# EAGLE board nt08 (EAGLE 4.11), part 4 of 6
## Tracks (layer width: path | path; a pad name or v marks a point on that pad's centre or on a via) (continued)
MC02\  (via drill 0.61) (continued)
  Bottom 0.254: v326.39,117.47 326.39,120.65 325.75,121.28 313.69,121.28 313.69,118.11 314.32,117.47 314.96,117.47 314.96,113.03 IC73.2 | v532.76,285.75 596.9,285.75 600.08,288.93 IC133.11 | v533.4,165.74 483.87,165.74 483.24,165.1 431.8,165.1 431.17,165.74 327.02,165.74 325.75,167 IC74.6
MF00  (via drill 0.61)
  Top 0.254: v525.78,160.02 525.78,157.48 IC115.9 | v429.26,162.56 424.81,167 v424.81,214.63 | v135.89,230.5 136.53,231.14 136.53,269.88 137.79,271.14 137.79,360.05 136.53,361.31 133.99,361.31 133.99,360.68 132.72,359.41 130.81,359.41 130.81,366.39 131.44,367.03 M916_9.V1
  Bottom 0.254: v525.78,160.02 523.24,162.56 v429.26,162.56 | v424.81,214.63 412.12,227.33 275.59,227.33 274.95,226.69 206.38,226.69 201.93,222.25 144.15,222.25 v135.89,230.5
MF00\  (via drill 0.61)
  Top 0.254: v226.06,15.88 217.81,24.13 217.81,107.95 | 217.81,107.95 217.81,140.34 218.44,140.97 v218.44,231.14 | v195.58,234.31 195.58,280.67 IC39.2 | v529.59,115.57 529.59,153.67 528.32,154.94 IC115.8 | v218.44,107.95 217.81,107.95
  Bottom 0.254: v226.06,15.88 227.33,15.88 229.87,13.34 233.04,13.34 234.31,14.61 IC46.2 | v218.44,231.14 215.26,234.31 v195.58,234.31 | v529.59,115.57 441.96,115.57 439.42,118.11 390.52,118.11 389.25,119.38 339.09,119.38 327.02,107.31 219.07,107.31 v218.44,107.95
MF01  (via drill 0.61)
  Top 0.254: v345.44,358.77 330.83,373.38 330.83,443.87 332.74,445.77 331.47,447.04 330.2,447.04 v330.2,446.4
  Bottom 0.254: v345.44,358.77 457.83,358.77 459.74,360.68 586.74,360.68 602.62,376.56 IC136.5 | v330.2,446.4 329.56,447.04 301.62,447.04 298.45,450.21 124.46,450.21 122.56,448.31 55.88,448.31 46.35,438.79 40.64,438.79 39.37,440.06 M916_10.A1
MF01\  (via drill 0.61)
  Top 0.254: v237.49,243.21 v237.49,227.97 237.49,175.9 240.03,173.35 240.03,109.22 241.3,107.95 241.3,17.78 242.57,16.51 IC46.5 | v216.53,246.38 214.63,248.28 v214.63,276.23 | v590.55,241.3 v590.55,360.68
  Bottom 0.254: v237.49,243.21 234.31,246.38 v216.53,246.38 | v214.63,276.23 210.82,280.04 205.1,280.04 203.84,281.31 IC39.5 | v590.55,360.68 605.79,375.92 IC136.6 | v590.55,241.3 582.93,233.68 466.73,233.68 461.64,228.6 275.59,228.6 274.32,227.33 238.12,227.33 v237.49,227.97
MF02  (via drill 0.61)
  Top 0.254: v405.13,401.32 403.86,402.59 v403.86,412.75 | v41.91,412.75 40.64,414.02 40.64,436.25 41.27,436.88 M916_10.B1
  Bottom 0.254: v405.13,401.32 408.31,401.32 415.93,393.7 596.9,393.7 605.15,385.44 IC136.9 | v403.86,412.75 403.23,412.12 57.15,412.12 55.88,413.38 42.55,413.38 v41.91,412.75
MF02\  (via drill 0.61)
  Top 0.254: v247.65,62.23 247.65,24.13 IC46.8 | v220.98,66.04 218.44,68.58 218.44,106.68 219.71,107.95 219.71,236.85 217.81,238.76 v217.81,286.38 217.81,307.98 v220.34,310.51 | v344.17,354.96 331.47,342.26 v331.47,313.06
  Bottom 0.254: v247.65,62.23 243.84,66.04 v220.98,66.04 | v217.81,286.38 215.26,288.93 208.91,288.93 IC39.8 | v344.17,354.96 527.68,354.96 532.13,359.41 607.06,359.41 607.06,378.46 607.7,379.1 608.33,379.1 608.33,383.54 IC136.8 | v331.47,313.06 330.83,313.69 223.52,313.69 v220.34,310.51
MK_BLK_MK
  Bottom 0.254: IC133.1 593.73,281.31 595,281.31 IC133.2
MKT  (via drill 0.61)
  Top 0.254: v329.56,81.92 330.2,82.55 330.2,133.99 328.93,135.25 v328.93,191.13 | v325.12,192.41 325.12,194.31 IC75.9 | v525.14,194.94 525.14,197.49 524.51,198.12 524.51,248.92 525.78,250.19 IC117.9 | v330.83,193.04 329.56,194.31 329.56,295.27 330.2,295.91 v330.2,361.31 330.2,444.5 v331.47,445.77
  Bottom 0.254: v329.56,81.92 324.49,81.92 323.21,80.64 IC72.10 | 328.3,191.77 327.66,192.41 v325.12,192.41 | 328.3,191.77 v328.93,191.13 | v525.14,194.94 521.97,191.77 330.83,191.77 | 330.83,191.77 328.3,191.77 | v330.2,361.31 323.21,361.31 320.68,358.77 IC78.4 | v330.83,193.04 330.83,191.77 | v331.47,445.77 330.83,445.13 302.26,445.13 299.72,447.68 252.09,447.68 251.46,447.04 62.87,447.04 62.87,436.88 61.59,435.61 59.69,435.61 58.42,434.34 M916_10.H2
MKT\  (via drill 0.61)
  Top 0.254: v281.94,385.44 281.94,393.7 283.21,394.97 IC66.5 | v247.01,382.9 246.38,382.27 246.38,288.29 248.92,285.75 v248.92,214.63 | v318.77,205.1 317.5,203.84 317.5,196.85 IC75.12 | v517.52,193.04 517.52,171.45 516.89,170.81 516.89,151.13 518.16,149.86 IC115.3 | v596.9,231.14 596.9,243.84 599.44,246.38 599.44,287.02 598.17,288.29 IC133.12
  Bottom 0.254: v281.94,385.44 279.4,382.9 v247.01,382.9 | v248.92,214.63 249.56,214 288.29,214 297.18,205.1 v318.77,205.1 | 514.35,196.22 513.72,196.85 469.26,196.85 468,195.58 328.3,195.58 IC75.8 327.02,196.22 325.75,197.49 319.4,197.49 318.13,196.22 IC75.12 | 514.35,196.22 v517.52,193.04 | v596.9,231.14 561.98,196.22 514.35,196.22
MKTK  (via drill 0.61)
  Top 0.254: v121.28,485.77 121.28,371.48 v120.65,370.84
  Bottom 0.254: v121.28,485.77 92.71,485.77 74.3,504.19 54.61,504.19 50.16,508.63 IC6.8 | v120.65,370.84 116.84,370.84 M916_9.P1
MKTK\  (via drill 0.61)
  Top 0.254: v50.8,58.42 54.61,62.23 54.61,123.19 53.34,124.46 53.34,179.71 55.24,181.61 55.24,238.76 57.15,240.66 57.15,261.62 53.34,265.43 53.34,454.66 53.98,455.3 53.98,501.01 46.99,508 IC6.9 | v161.29,514.35 161.29,553.72 160.02,554.99 IC32.11
  Bottom 0.254: v50.8,58.42 38.1,58.42 33.66,53.98 IC10.1 | v161.29,514.35 160.66,514.99 119.38,514.99 115.57,511.18 48.9,511.18 47.62,509.9 IC6.9
MOVE\  (via drill 0.61)
  Top 0.254: v539.12,421 537.21,419.1 537.21,325.75 537.85,325.12 537.85,178.44 539.75,176.53 539.75,76.2 539.12,75.56 v539.12,19.68
  Bottom 0.254: 539.12,20.32 557.53,20.32 559.43,22.23 IC123.11 | 539.12,20.32 56.52,20.32 55.88,20.95 40.01,20.95 38.73,22.23 IC9.12 | v539.12,421 545.47,421 IC124.1 | v539.12,19.68 539.12,20.32
MR00  (via drill 0.61)
  Top 0.254: v268.61,537.85 268.61,540.38 246.38,562.61 246.38,572.77 245.11,574.04 IC57.9 | v291.46,522.61 295.91,518.16 295.91,323.85 297.18,322.58 v297.18,262.89 | v313.69,262.25 317.5,258.44 317.5,252.73 IC76.12
  Bottom 0.254: v268.61,537.85 283.85,522.61 v291.46,522.61 | v297.18,262.89 297.81,262.25 v313.69,262.25
MR00\  (via drill 0.61)
  Top 0.254: v162.56,458.47 162.56,407.67 160.02,405.13 IC30.11 | v187.96,459.74 189.87,461.64 189.87,537.85 199.39,547.37 199.39,557.53 219.71,577.85 247.65,577.85 247.65,576.58 IC57.8
  Bottom 0.254: v162.56,458.47 163.83,459.74 v187.96,459.74
MR01  (via drill 0.61)
  Top 0.254: v476.25,285.12 476.25,265.43 474.98,264.16 IC108.2 | v89.53,347.35 89.53,369.57 90.17,370.2 M916_9.E1 | v406.4,342.26 v406.4,296.55
  Bottom 0.254: v476.25,285.12 450.21,285.12 446.4,288.93 IC95.9 445.13,290.19 443.87,291.46 411.48,291.46 v406.4,296.55 | v89.53,347.35 93.34,343.54 125.73,343.54 126.36,344.17 185.42,344.17 186.69,345.44 228.6,345.44 230.5,347.35 286.38,347.35 288.29,345.44 346.07,345.44 348.62,347.98 400.69,347.98 v406.4,342.26
MR01\  (via drill 0.61)
  Top 0.254: v445.77,256.54 447.04,257.81 447.04,283.21 441.96,288.29 441.96,290.83 442.6,291.46 448.31,291.46 448.31,290.83 IC95.8 | v170.18,465.45 172.72,462.92 172.72,363.22 173.35,362.58 173.35,249.56 v172.72,248.92
  Bottom 0.254: 316.87,245.75 318.77,247.65 353.06,247.65 358.14,252.73 377.19,252.73 379.73,255.27 396.24,255.27 397.51,256.54 v445.77,256.54 | 316.87,245.75 315.6,244.47 IC76.2 | v170.18,465.45 161.93,465.45 155.57,471.81 IC31.2 | v172.72,248.92 289.56,248.92 292.74,245.75 316.87,245.75
N$1  (via drill 0.61)
  Top 0.254: v265.43,188.59 264.16,189.87 v264.16,243.21 | v226.06,247.65 222.88,250.82 222.88,288.93 224.79,290.83 224.79,296.55 225.43,297.18 225.43,349.25 224.79,349.88 224.79,389.25 224.16,389.89 v224.16,509.9
  Bottom 0.254: v265.43,188.59 276.23,188.59 277.5,187.32 IC61.3 | v264.16,243.21 259.71,247.65 v226.06,247.65 | v224.16,509.9 231.78,509.9 IC55.1
N$2  (via drill 0.61)
  Top 0.254: IC120.13 516.25,422.27 517.52,422.27 IC120.12 | v535.3,421 535.3,326.39 537.21,324.49 537.21,13.34 525.14,13.34 524.51,13.97 524.51,20.32 523.24,21.59 IC112.10 | IC120.10 523.88,422.27 525.14,422.27 IC120.9
  Bottom 0.254: v535.3,421 527.68,421 | 527.68,421 526.41,422.27 IC120.9 | 527.68,421 520.07,421 518.79,422.27 IC120.12
N$3  (via drill 0.61)
  Top 0.254: v45.09,537.85 38.1,530.86 38.1,474.98 39.37,473.71 IC15.3 | v282.57,542.92 285.75,546.1 285.75,547.37 IC69.6
  Bottom 0.254: v45.09,537.85 48.9,541.65 210.19,541.65 211.46,542.92 v282.57,542.92
N$4
  Top 0.254: M916_19.R2 -0.64,221.62 1.27,223.52 1.27,224.16 M916_19.S2
N$5  (via drill 0.61)
  Top 0.254: v485.14,434.98 v488.31,438.15
  Bottom 0.254: v488.31,438.15 510.54,438.15 525.14,452.75 IC121.6 | v485.14,434.98 478.79,428.62 283.85,428.62 273.69,418.46 94.61,418.46 93.34,419.74 59.69,419.74 58.42,421 M916_2.H2
N$6  (via drill 0.61)
  Top 0.254: IC121.9 525.14,460.38 523.88,460.38 IC121.10 522.61,460.38 516.89,454.66 | 516.89,460.38 517.52,460.38 IC121.12 | 516.89,460.38 516.25,460.38 IC121.13 | v515.62,426.08 516.89,427.36 516.89,454.66 | 516.89,454.66 516.89,460.38
  Bottom 0.254: v515.62,426.08 383.54,426.08 372.11,414.65 144.78,414.65 144.15,414.02 11.43,414.02 -14.61,387.99 -44.45,387.99 -44.45,230.5 -36.83,222.88 -28.57,222.88 -27.3,221.62 M916_19.F2
N$7
  Top 0.254: IC16.5 82.55,16.51 82.55,19.05 80.01,21.59 IC16.11 80.01,24.13 80.01,90.17 IC17.4
N$8
  Top 0.254: IC123.1 551.82,14.61 530.86,-6.35 -34.92,-6.35 -34.92,454.66 -27.3,462.28 M916_23.F2
N$10  (via drill 0.61)
  Top 0.254: v375.92,153.67 v375.92,38.1 | v373.38,156.21 374.01,156.84 374.01,320.68 381,327.66 381,454.66 384.81,458.47 v384.81,471.17
  Bottom 0.254: v375.92,38.1 370.2,32.38 314.32,32.38 313.06,33.66 IC71.1 | v373.38,156.21 v375.92,153.67 | v384.81,471.17 390.52,476.88 404.5,476.88 407.04,479.43 IC90.8
N$11  (via drill 0.61)
  Top 0.254: v355.6,36.83 374.65,36.83 374.65,154.94 376.56,156.84 376.56,318.13 381.63,323.21 381.63,454.02 386.08,458.47 v386.08,476.25
  Bottom 0.254: v355.6,36.83 325.12,36.83 323.21,34.92 IC71.5 | v386.08,476.25 387.35,477.52 402.59,477.52 403.86,478.79 403.86,481.96 401.95,481.96 400.69,480.69 IC90.11
N$12
  Top 0.254: M916_23.D2 -32.38,462.92 -30.48,464.82 -30.48,465.45 M916_23.E2
N$13  (via drill 0.61)
  Top 0.254: v289.56,219.07 289.56,196.85 288.29,195.58 IC61.8
  Bottom 0.254: M916_1.H2 97.79,224.16 100.33,221.62 M916_1.J2 100.97,221.62 103.5,224.16 M916_1.K2 104.14,224.79 106.05,224.79 107.31,226.06 118.75,226.06 121.92,222.88 133.35,222.88 133.35,220.34 134.62,219.07 v289.56,219.07
N$14
  Top 0.254: M916_2.D2 48.9,418.46 50.8,420.37 50.8,421 M916_2.E2
N$15  (via drill 0.61)
  Top 0.254: v515.62,18.41 515.62,21.59 IC112.13 | v74.3,18.41 71.12,21.59 71.12,87.63 73.66,90.17 73.66,212.72 67.94,218.44 67.94,413.38 v64.77,416.56
  Bottom 0.254: v515.62,18.41 514.99,19.05 74.93,19.05 v74.3,18.41 | v64.77,416.56 56.52,416.56 55.24,417.83 M916_2.F2
N$16  (via drill 0.61)
  Top 0.254: IC18.4 80.64,243.21 81.92,243.21 IC18.5 82.55,242.57 83.82,241.3 83.82,238.12 83.19,237.49 83.19,223.52 83.82,222.88 83.82,220.34 83.19,219.71 83.19,214.63 80.01,211.46 80.01,149.86 v81.28,148.59 | v518.16,26.67 518.16,24.13 IC112.12 | v226.06,28.57 222.25,32.38 v222.25,147.32
  Bottom 0.254: v518.16,26.67 516.89,27.94 286.38,27.94 285.75,28.57 v226.06,28.57 | v222.25,147.32 220.98,148.59 v81.28,148.59
N$17  (via drill 0.61)
  Top 0.254: IC77.3 317.5,267.97 320.04,270.51 320.04,273.05 IC77.11 320.04,275.59 320.04,298.45 v316.23,302.26
  Bottom 0.254: v316.23,302.26 182.88,302.26 181.61,303.53 97.16,303.53 95.89,302.26 14.61,302.26 13.97,302.89 -25.4,302.89 -32.38,309.88 M916_21.D2
N$18  (via drill 0.61)
  Top 0.254: v281.94,216.53 281.31,215.9 281.31,196.22 280.67,195.58 IC61.11 | v119.38,219.07 v121.92,216.53
  Bottom 0.254: M916_1.P2 115.57,224.16 110.49,224.16 M916_1.M2 109.22,224.16 107.95,222.88 107.95,221.62 112.39,221.62 M916_1.N2 113.67,220.98 117.47,220.98 v119.38,219.07 | v281.94,216.53 281.31,215.9 133.35,215.9 132.72,216.53 v121.92,216.53
N$19
  Bottom 0.254: M916_1.H1 96.52,230.5 96.52,226.06 95.89,225.43 95.89,220.34 99.06,220.34 99.69,219.71 104.78,219.71 106.05,220.98 M916_1.L2
N$20
  Top 0.254: M916_2.R2 80.64,418.46 82.55,420.37 82.55,421 M916_2.S2
N$21
  Bottom 0.254: M916_1.D2 88.27,221.62 90.81,224.16 M916_1.E2
N$22  (via drill 0.61)
  Top 0.254: v125.09,465.45 124.46,464.82 124.46,344.17 128.27,340.36 128.27,315.6 127.64,314.96 127.64,291.46 130.18,288.93 130.18,217.17 129.54,216.53 127.64,216.53 127.64,219.71 126.36,220.98 M916_1.T2
  Bottom 0.254: v125.09,465.45 113.03,477.52 93.34,477.52 92.71,476.88 40.01,476.88 37.47,479.43 IC15.13
N$23  (via drill 0.61)
  Top 0.254: v32.38,465.45 30.48,463.55 30.48,421.64 28.57,419.74 28.57,389.25 29.21,388.62 29.21,356.24 27.3,354.33 v27.3,233.04
  Bottom 0.254: v32.38,465.45 37.47,465.45 43.81,471.81 IC15.5 | v27.3,233.04 34.29,226.06 91.44,226.06 93.34,224.16 93.34,221.62 M916_1.F2
N$24  (via drill 0.61)
  Top 0.254: v527.05,506.73 527.05,387.35 528.32,386.08 IC119.8
  Bottom 0.254: v527.05,506.73 526.41,506.1 314.96,506.1 306.7,497.84 304.8,497.84 M916_12.K2
N$25
  Bottom 0.254: M916_1.R2 120.02,220.98 120.65,220.34 124.46,220.34 125.09,219.71 130.18,219.71 131.44,220.98 M916_1.V2
N$26
  Top 0.254: M916_1.S2 121.92,224.79 121.92,230.5 M916_1.S1
N$27
  Bottom 0.254: M916_21.N2 -6.99,310.51 -5.71,311.79 0,311.79 1.27,313.06 M916_21.S2
N$28  (via drill 0.61)
  Top 0.254: v315.6,51.44 315.6,70.48 314.96,71.12 IC72.2 | v448.31,56.52 450.21,58.42 450.21,323.85 v453.39,327.02
  Bottom 0.254: v315.6,51.44 316.23,50.8 440.69,50.8 446.4,56.52 v448.31,56.52 | v453.39,327.02 469.26,327.02 471.81,329.56 475.62,329.56 476.88,328.3 IC109.12
N$29
  Top 0.254: M916_12.D2 288.93,494.67 290.83,496.57 290.83,497.2 M916_12.E2
N$30
  Bottom 0.254: IC122.3 518.79,511.18 520.07,512.45 523.88,512.45 524.51,511.81 524.51,506.73 309.25,506.73 297.18,494.67 295.27,494.67 M916_12.F2
N$31  (via drill 0.61)
  Top 0.254: IC19.10 84.45,268.61 85.72,268.61 IC19.9 86.36,270.51 86.36,285.75 92.71,292.1 92.71,330.2 v93.98,331.47 | v512.45,501.01 520.7,509.27 IC122.4 | v299.72,484.5 298.45,483.24 v298.45,340.36
  Bottom 0.254: v512.45,501.01 499.11,487.68 417.19,487.68 414.02,484.5 v299.72,484.5 | v298.45,340.36 297.81,341 207.01,341 197.49,331.47 v93.98,331.47
N$33  (via drill 0.61)
  Top 0.254: v5.08,543.56 2.54,546.1 IC7.10 | v245.11,546.74 266.7,525.14 v266.7,398.14
  Bottom 0.254: v5.08,543.56 6.35,542.29 104.14,542.29 113.03,551.18 125.73,551.18 127,549.91 127,546.1 244.47,546.1 v245.11,546.74 | v266.7,398.14 283.85,398.14 285.12,396.88 IC66.6
N$34  (via drill 0.61)
  Top 0.254: v353.06,24.77 344.81,33.02 344.81,225.43 342.26,227.97 v342.26,314.96 | v7.62,307.98 3.81,307.98 3.81,385.44 4.45,386.08 M916_22.T2
  Bottom 0.254: v353.06,24.77 353.69,25.4 562.61,25.4 564.51,23.5 IC123.9 | v342.26,314.96 151.13,314.96 147.32,311.15 14.61,311.15 11.43,307.98 v7.62,307.98
N$35
  Bottom 0.254: IC8.9 4.45,586.11 2.54,588.01 -8.89,588.01 -46.35,550.54 -46.35,-6.99 456.56,-6.99 474.98,11.43 485.14,11.43 487.05,13.34 IC104.8
N$36  (via drill 0.61)
  Top 0.254: v495.94,432.44 496.57,431.8 496.57,196.22 500.38,192.41 v500.38,149.86
  Bottom 0.254: v495.94,432.44 492.12,436.25 447.68,436.25 446.4,434.98 IC99.6 | v500.38,149.86 501.01,150.5 513.72,150.5 514.99,149.22 IC115.2
N$37
  Top 0.254: M916_12.R2 320.68,494.67 322.58,496.57 322.58,497.2 M916_12.S2
N$38
  Top 0.254: IC116.3 518.16,204.47 518.16,209.55 IC116.12
N$39
  Bottom 0.254: IC116.13 516.25,210.19 521.34,205.1 523.88,205.1 525.14,203.84 IC116.6
N$40
  Bottom 0.254: M916_20.M2 -10.16,236.85 -8.89,235.59 9.53,235.59 10.79,234.31 M916_20.V2
N$41
  Bottom 0.254: M916_20.P1 -3.81,243.21 -2.54,241.94 9.53,241.94 10.79,240.66 M916_20.V1
N$42  (via drill 0.61)
  Top 0.254: v483.87,120.02 483.87,113.03 485.14,111.76 IC106.6
  Bottom 0.254: v483.87,120.02 479.43,120.02 478.15,118.75 IC106.12
N$43
  Top 0.254: IC17.3 77.47,92.71 77.47,97.79 IC17.12
N$44  (via drill 0.61)
  Top 0.254: v474.98,85.72 478.79,89.53 478.79,111.76 480.06,113.03 480.06,116.84 IC106.11
  Bottom 0.254: v474.98,85.72 319.4,85.72 314.96,81.28 IC72.13
N$45
  Bottom 0.254: IC17.13 75.56,98.42 76.83,97.16 85.72,97.16 87,98.42 IC17.8
N$46  (via drill 0.61)
  Top 0.254: v34.29,160.66 40.64,154.31 40.64,123.19 40.01,122.56 40.01,118.75 IC11.11
  Bottom 0.254: v34.29,160.66 -45.72,160.66 -45.72,549.91 -8.26,587.38 -4.45,587.38 -3.17,586.11 IC8.12
N$47  (via drill 0.61)
  Top 0.254: v327.66,476.88 343.54,461.01 v343.54,445.13 | v440.69,446.4 441.96,445.13 441.96,436.88 443.23,435.61 IC99.5
  Bottom 0.254: v327.66,476.88 290.19,476.88 IC68.8 | v343.54,445.13 344.17,445.77 415.29,445.77 415.93,446.4 v440.69,446.4
N$48  (via drill 0.61)
  Top 0.254: v358.14,38.1 360.68,40.64 v360.68,184.78
  Bottom 0.254: v358.14,38.1 355.6,35.56 354.96,35.56 354.33,36.2 327.02,36.2 325.75,34.92 IC71.6 | v360.68,184.78 475.62,184.78 476.25,185.42 476.25,188.59 478.15,188.59 479.43,187.32 IC107.4
N$49  (via drill 0.61)
  Top 0.254: v262.89,479.43 257.81,474.35 257.81,393.06 255.27,390.52 255.27,340.36 257.18,338.45 257.18,304.17 263.52,297.81 263.52,251.46 262.89,250.82 262.89,233.68 263.52,233.04 263.52,163.83 267.33,160.02 267.33,44.45 265.43,42.55 v265.43,9.53
  Bottom 0.254: v262.89,479.43 282.57,479.43 283.85,478.15 IC68.10 | v265.43,9.53 266.7,8.26 323.21,8.26 327.02,4.45 IC70.8
N$50  (via drill 0.61)
  Top 0.254: v516.89,367.67 516.89,254 518.16,252.73 IC117.12
  Bottom 0.254: v516.89,367.67 502.29,382.27 480.06,382.27 478.15,384.18 IC110.12
N$51  (via drill 0.61)
  Top 0.254: v328.93,97.79 328.93,82.55 327.66,81.28 IC72.8 | v466.09,103.5 470.54,107.95 v470.54,260.35
  Bottom 0.254: v328.93,97.79 334.64,103.5 v466.09,103.5 | v470.54,260.35 471.17,260.99 478.15,260.99 479.43,262.25 IC108.4
N$52  (via drill 0.61)
  Top 0.254: v477.52,189.87 476.25,191.13 476.25,250.19 474.35,252.09 474.35,258.44 477.52,261.62 IC108.3
  Bottom 0.254: v477.52,189.87 481.96,189.87 484.5,187.32 IC107.6
N$53
  Bottom 0.254: IC117.13 516.25,250.82 521.34,245.75 523.88,245.75 525.14,244.47 IC117.6
N$54
  Top 0.254: IC106.3 477.52,111.76 478.79,113.03 478.79,257.81 482.6,261.62 IC108.5
N$55  (via drill 0.61)
  Top 0.254: v382.27,479.43 386.08,483.24 386.08,494.03 387.35,495.3 388.62,495.3 388.62,384.81 382.9,379.1 382.9,203.2 377.19,197.49 377.19,38.1 v334.01,-5.08
  Bottom 0.254: v382.27,479.43 288.93,479.43 287.65,478.15 IC68.9 | v334.01,-5.08 333.38,-5.71 327.02,-5.71 325.75,-4.45 IC70.6
N$56  (via drill 0.61)
  Top 0.254: v13.34,471.81 13.34,468.63 9.53,464.82 9.53,290.19 6.99,290.19 5.71,291.46 IC2.6 | v281.94,485.14 281.94,478.79 IC68.11
  Bottom 0.254: v13.34,471.81 13.97,472.44 22.86,472.44 34.92,484.5 177.16,484.5 177.8,485.14 v281.94,485.14
N$58  (via drill 0.61)
  Top 0.254: v57.78,478.15 59.69,476.25 59.69,328.3 60.33,327.66 v60.33,306.07 | v254.63,306.07 255.27,305.44 255.27,219.07 261.62,212.72 v261.62,187.96
  Bottom 0.254: v57.78,478.15 48.9,478.15 47.62,479.43 IC15.9 | v60.33,306.07 157.48,306.07 158.12,306.7 254,306.7 v254.63,306.07 | v261.62,187.96 265.43,184.15 269.88,184.15 271.14,182.88 283.21,182.88 285.75,185.42 IC61.6
N$59  (via drill 0.61)
  Top 0.254: v511.18,13.34 495.3,29.21 v495.3,193.04
  Bottom 0.254: v511.18,13.34 516.25,13.34 517.52,14.61 IC112.3 | v495.3,193.04 492.12,196.22 481.96,196.22 480.69,194.94 IC107.11
N$60  (via drill 0.61)
  Top 0.254: v456.56,76.83 457.2,77.47 v457.2,267.97 | v486.41,267.33 487.68,268.61 487.68,269.24 IC108.8
  Bottom 0.254: v456.56,76.83 316.87,76.83 313.06,73.03 IC72.1 | v457.2,267.97 457.83,267.33 v486.41,267.33
N$61  (via drill 0.61)
  Top 0.254: v456.56,69.22 458.47,71.12 458.47,142.24 459.74,143.51 459.74,256.54 464.19,260.99 464.19,358.14 466.09,360.05 v466.09,373.38
  Bottom 0.254: v456.56,69.22 455.93,69.85 322.58,69.85 320.68,71.75 IC72.4 | v466.09,373.38 471.81,379.1 483.24,379.1 484.5,377.82 IC110.6
N$62  (via drill 0.61)
  Top 0.254: v328.93,74.3 328.93,44.45 327.66,43.18 IC71.8
  Bottom 0.254: v328.93,74.3 324.49,74.3 323.21,73.03 IC72.5
N$63  (via drill 0.61)
  Top 0.254: v305.44,177.8 305.44,195.58 307.98,198.12 307.98,305.44 306.7,306.7 306.7,367.67 315.6,367.67 316.23,367.03 316.23,360.68 317.5,359.41 IC78.3
  Bottom 0.254: v305.44,177.8 320.04,177.8 321.94,175.9 IC74.10
N$64  (via drill 0.61)
  Top 0.254: v97.16,32.38 88.27,23.5 IC16.8 | v172.72,41.27 173.99,42.55 173.99,105.41 173.35,106.05 173.35,116.2 176.53,119.38 v176.53,259.08 | v220.98,262.25 222.25,263.52 v222.25,358.14 | IC65.5 282.57,357.5 281.31,357.5 IC65.4
  Bottom 0.254: v97.16,32.38 106.05,41.27 v172.72,41.27 | v176.53,259.08 179.71,262.25 v220.98,262.25 | v222.25,358.14 224.16,360.05 278.76,360.05 280.04,358.77 IC65.4
N$65
  Bottom 0.254: IC107.12 478.15,193.68 479.43,192.41 485.77,192.41 487.05,193.68 IC107.8
N$66  (via drill 0.61)
  Top 0.254: v177.8,356.24 178.44,355.6 178.44,264.16 180.34,262.25 180.34,258.44 177.8,255.91 177.8,12.06 80.64,12.06 78.11,14.61 IC16.3 | IC65.2 274.95,357.5 273.69,357.5 IC65.1
  Bottom 0.254: v177.8,356.24 212.72,356.24 214,357.5 221.62,357.5 222.25,356.87 273.05,356.87 IC65.1
N$67  (via drill 0.61)
  Top 0.254: v-18.41,304.17 -18.41,235.59 -19.68,234.31 M916_20.J2
  Bottom 0.254: v-18.41,304.17 2.54,304.17 10.16,311.79 127,311.79 132.08,316.87 337.82,316.87 340.36,319.4 364.49,319.4 365.12,318.77 379.1,318.77 387.35,310.51 606.42,310.51 607.7,309.25 IC134.8
N$68
  Top 0.254: M916_20.D2 -32.38,234.31 -27.94,234.31 -27.94,236.85 -24.13,240.66 -24.13,243.21 M916_20.H1
N$69
  Bottom 0.254: M916_20.A1 -41.91,243.21 -36.83,243.21 M916_20.C1
N$70  (via drill 0.61)
  Top 0.254: v97.16,300.99 98.42,302.26 98.42,374.65 112.39,388.62 v112.39,420.37 | v280.67,426.72 284.48,430.53 284.48,450.85 286.38,452.75 286.38,469.26 IC68.6
  Bottom 0.254: v97.16,300.99 86.36,300.99 83.19,297.81 6.99,297.81 5.71,299.08 IC2.9 | v112.39,420.37 120.02,427.99 143.51,427.99 144.78,426.72 v280.67,426.72
N$71  (via drill 0.61)
  Top 0.254: v347.98,508.63 347.98,507.37 326.39,485.77 326.39,360.68 325.12,359.41 IC78.6
  Bottom 0.254: v347.98,508.63 348.62,508 510.54,508 512.45,509.9 IC122.1
N$72  (via drill 0.61)
  Top 0.254: v0,321.94 0,300.99 IC2.11 | v275.59,323.85 276.86,325.12 276.86,467.36 278.13,468.63 278.13,474.98 279.4,476.25 IC68.12
  Bottom 0.254: v0,321.94 3.17,325.12 72.39,325.12 73.66,323.85 v275.59,323.85
N$73  (via drill 0.61)
  Top 0.254: v283.21,292.74 283.21,290.83 IC63.10 | v270.51,292.1 270.51,267.33 271.14,266.7 271.14,254.63 269.88,253.37 269.88,183.51 271.78,181.61 v271.78,113.03
  Bottom 0.254: v283.21,292.74 282.57,292.1 v270.51,292.1 | v271.78,113.03 272.42,112.39 283.85,112.39 285.12,111.12 IC60.6
N$76
  Top 0.254: IC118.3 518.16,318.77 519.43,317.5 519.43,214.63 521.97,212.09 521.97,180.97 521.34,180.34 521.34,158.12 521.97,157.48 521.97,120.65 520.7,119.38 IC114.11
N$77  (via drill 0.61)
  Top 0.254: v166.37,299.72 168.91,302.26 v168.91,360.68
  Bottom 0.254: v166.37,299.72 102.87,299.72 100.33,302.26 97.16,302.26 96.52,301.62 9.53,301.62 8.26,300.36 IC2.8 | v168.91,360.68 172.09,363.86 283.85,363.86 285.12,365.12 IC65.9
N$78  (via drill 0.61)
  Top 0.254: v275.59,389.25 275.59,367.03 IC65.13 | v332.11,392.43 345.44,405.76 v345.44,491.49 | v512.45,502.29 515.62,505.46 515.62,509.27 IC122.2
  Bottom 0.254: v275.59,389.25 278.76,392.43 v332.11,392.43 | v345.44,491.49 346.71,492.76 389.89,492.76 393.06,495.94 506.1,495.94 v512.45,502.29
N$79  (via drill 0.61)
  Top 0.254: v547.37,121.28 546.74,121.92 546.74,419.74 547.37,420.37 v547.37,515.62
  Bottom 0.254: v547.37,121.28 526.41,121.28 523.88,118.75 IC114.10 | v547.37,515.62 542.29,520.7 485.14,520.7 483.24,518.79 IC111.10
N$80  (via drill 0.61)
  Top 0.254: v196.85,563.88 v177.8,582.93 | v290.19,560.07 309.25,541.02 309.25,376.56 318.77,367.03 318.77,300.99 321.94,297.81 v321.94,294.64 | v356.24,292.74 358.14,290.83 358.14,223.52 360.68,220.98 360.68,209.55 363.86,206.38 363.86,142.88 368.3,138.43 368.3,135.89 M916_15.U2
  Bottom 0.254: v177.8,582.93 -2.54,582.93 -4.45,584.84 IC8.13 | v196.85,563.88 200.66,560.07 v290.19,560.07 | v321.94,294.64 323.85,292.74 v356.24,292.74
N$81
  Top 0.254: IC108.12 477.52,271.78 480.69,274.95 480.69,318.13 481.33,318.77 481.33,515.62 480.06,516.89 IC111.11
N$82  (via drill 0.61)
  Top 0.254: v291.46,507.37 288.93,509.9 288.93,546.74 289.56,547.37 289.56,552.45 288.29,553.72 288.29,554.99 IC69.8
  Bottom 0.254: v291.46,507.37 520.07,507.37 522.61,509.9 IC122.5
N$83
  Top 0.254: IC5.12 -2.54,450.85 -5.71,454.02 -5.71,534.03 -3.81,535.94 -3.81,568.96 3.81,576.58 3.81,580.39 7.62,584.2 IC8.8
N$84
  Bottom 0.254: IC11.3 38.73,109.86 40.01,109.86 IC11.4
N$85  (via drill 0.61)
  Top 0.254: v313.69,370.84 317.5,367.03 IC78.12 | v136.53,360.05 136.53,271.14 134.62,269.24 134.62,221.62 136.53,219.71 136.53,178.44 135.25,177.16 v135.25,114.94
  Bottom 0.254: IC11.2 36.2,109.86 37.47,108.58 43.81,108.58 45.09,109.86 IC11.6 46.35,109.86 50.8,105.41 82.55,105.41 84.45,107.31 127.64,107.31 v135.25,114.94 | v313.69,370.84 264.16,370.84 263.52,370.2 146.69,370.2 v136.53,360.05
N$86
  Top 0.254: IC69.13 275.59,557.53 283.85,565.78 283.85,574.67 284.48,575.31 312.42,575.31 312.42,497.84 314.96,495.3 314.96,372.11 320.04,367.03 IC78.11
N$88
  Top 0.254: M916_23.R2 -0.64,462.92 1.27,464.82 1.27,465.45 M916_23.S2
N$91
  Top 0.254: IC60.11 280.67,119.38 279.4,120.65 279.4,198.12 280.67,199.39 280.67,241.3 279.4,242.57 279.4,317.5 280.67,318.77 IC64.4
N$92  (via drill 0.61)
  Top 0.254: v268.61,49.53 267.97,50.16 267.97,181.61 266.7,182.88 266.7,233.68 266.06,234.31 266.06,248.92 v267.97,250.82
  Bottom 0.254: v268.61,49.53 273.05,49.53 280.04,42.55 IC59.11 | v267.97,250.82 270.51,253.37 281.31,253.37 282.57,252.09 IC62.10
N$93  (via drill 0.61)
  Top 0.254: 596.9,33.02 596.26,32.38 594.36,32.38 594.36,35.56 593.09,36.83 593.09,40.64 IC126.14 | 596.9,33.02 597.53,33.66 IC126.3 | v599.44,85.72 599.44,76.2 596.9,73.66 596.9,33.02
  Bottom 0.254: v599.44,85.72 609.6,85.72 609.6,111.76 607.06,114.3 607.06,137.79 605.79,139.06 605.79,157.48 IC129.6
N$94  (via drill 0.61)
  Top 0.254: v611.5,166.37 610.87,165.74 610.87,85.09 609.6,83.82 609.6,36.83 608.33,35.56 IC126.7
  Bottom 0.254: IC126.7 608.33,35.56 603.25,40.64 IC126.10 | v611.5,166.37 608.97,166.37 IC129.8
N$95  (via drill 0.61)
  Top 0.254: v610.87,83.82 612.77,85.72 612.77,236.85 608.33,241.3 IC131.8
  Bottom 0.254: IC127.3 598.17,73.66 593.09,78.74 IC127.14 593.73,80.64 596.26,83.19 610.24,83.19 v610.87,83.82
N$96  (via drill 0.61)
  Top 0.254: v599.44,189.23 599.44,113.03 598.17,111.76 IC128.3
  Bottom 0.254: IC128.3 598.17,111.76 593.09,116.84 IC128.14 | v599.44,189.23 605.79,195.58 IC130.6
N$97
  Top 0.254: IC59.3 278.13,35.56 276.86,36.83 276.86,104.14 281.94,109.22 281.94,215.26 283.21,216.53 283.21,217.17 281.31,219.07 281.31,243.21 IC62.4
N$99  (via drill 0.61)
  Top 0.254: v609.6,229.87 610.24,229.24 610.24,113.67 608.33,111.76 IC128.7
  Bottom 0.254: IC128.10 603.25,116.84 608.33,111.76 IC128.7 | v609.6,229.87 605.79,233.68 IC131.6
N$100
  Top 0.254: IC130.8 608.33,203.2 609.6,201.93 609.6,114.3 607.06,111.76 607.06,74.93 608.33,73.66 IC127.7
  Bottom 0.254: IC127.10 603.25,78.74 608.33,73.66 IC127.7
N$101
  Top 0.254: IC128.5 603.25,109.22 604.52,107.95 604.52,74.93 603.25,73.66 IC127.5 603.25,71.12 604.52,69.85 604.52,37.47 603.25,36.2 603.25,35.56 IC126.5
  Bottom 0.254: IC123.6 565.78,15.88 582.29,32.38 601.35,32.38 602.62,33.66 IC126.5
N$103  (via drill 0.61)
  Top 0.254: 591.82,69.85 591.82,36.83 593.09,35.56 IC126.1 | 591.82,69.85 593.09,71.12 IC127.1 | 591.82,69.85 591.82,107.95 593.09,109.22 IC128.1 | v544.83,139.06 543.56,140.34 543.56,182.88 541.65,184.78 541.65,525.78 520.7,525.78 519.43,524.51 519.43,520.7 518.16,519.43 IC122.12
  Bottom 0.254: v544.83,139.06 572.77,111.12 592.46,111.12 IC128.1
N$104  (via drill 0.61)
  Top 0.254: v451.49,338.45 452.75,339.73 v452.75,497.2
  Bottom 0.254: v451.49,338.45 448.94,338.45 IC96.8 | v452.75,497.2 445.13,497.2 443.87,498.48 IC101.10
N$105
  Top 0.254: IC4.9 5.08,425.45 5.71,426.08 5.71,440.06 6.35,440.69 6.35,575.31 5.08,576.58 IC8.6
N$106  (via drill 0.61)
  Top 0.254: v26.67,189.87 26.67,157.48 30.48,153.67 30.48,29.21 35.56,24.13 IC9.13 | v21.59,194.94 20.95,195.58 20.95,307.98 19.68,309.25 19.68,423.55 v20.32,424.18
  Bottom 0.254: v26.67,189.87 v21.59,194.94 | v20.32,424.18 8.26,424.18 IC4.8
N$107  (via drill 0.61)
  Top 0.254: v-15.88,476.88 -44.45,448.31 v-44.45,70.48 | v48.26,49.53 48.26,24.13 IC9.8
  Bottom 0.254: v-15.88,476.88 12.06,504.82 34.92,504.82 38.73,508.63 IC6.12 | v-44.45,70.48 -23.5,49.53 v48.26,49.53
N$108
  Top 0.254: IC103.8 448.94,584.84 504.82,528.96 515.62,528.96 515.62,519.43 IC122.13
N$109  (via drill 0.61)
  Top 0.254: v563.25,46.35 563.88,45.72 563.88,17.78 562.61,16.51 IC123.5
  Bottom 0.254: v563.25,46.35 487.05,46.35 485.77,45.09 IC105.6
N$111  (via drill 0.61)
  Top 0.254: v38.1,44.45 36.83,45.72 36.83,58.42 35.56,59.69 IC10.13
  Bottom 0.254: v38.1,44.45 57.15,44.45 58.42,43.18 181.61,43.18 182.88,41.91 212.72,41.91 216.53,38.1 314.96,38.1 316.23,39.37 431.17,39.37 439.42,31.11 566.42,31.11 566.42,21.59 560.71,15.88 IC123.4
N$112  (via drill 0.61)
  Top 0.254: v293.37,36.2 292.74,36.83 292.74,114.94 295.91,118.11 295.91,187.96 296.55,188.59 296.55,255.91 299.72,259.08 299.72,308.61 300.36,309.25 300.36,328.3 v300.99,328.93
  Bottom 0.254: v293.37,36.2 287.65,36.2 286.38,34.92 IC59.6 | v300.99,328.93 300.36,329.56 285.12,329.56 283.85,328.3 IC64.10
N$113  (via drill 0.61)
  Top 0.254: v280.67,265.43 280.67,280.67 IC63.4 | v290.19,260.35 292.74,257.81 292.74,191.13 290.19,188.59 290.19,51.44 290.83,50.8 290.83,34.29 288.93,32.38 287.02,32.38 287.02,39.37 288.29,40.64 IC59.8
  Bottom 0.254: v280.67,265.43 285.75,260.35 v290.19,260.35
N$114  (via drill 0.61)
  Top 0.254: v38.1,386.08 37.47,386.71 37.47,457.2 40.64,460.38 40.64,477.52 41.91,478.79 IC15.11 | v-36.2,327.02 -38.1,325.12 v-38.1,76.83
  Bottom 0.254: v38.1,386.08 -5.08,342.9 -20.32,342.9 v-36.2,327.02 | v-38.1,76.83 -20.95,59.69 31.75,59.69 32.38,59.05 46.35,59.05 47.62,60.33 IC10.8
N$115  (via drill 0.61)
  Top 0.254: v549.27,236.85 549.91,236.22 549.91,118.11 555.62,112.39 555.62,24.77 556.26,24.13 556.26,17.78 557.53,16.51 IC123.3
  Bottom 0.254: v549.27,236.85 542.92,236.85 528.96,250.82 IC117.8
N$116  (via drill 0.61)
  Top 0.254: v508,246.38 507.37,245.75 507.37,18.41 512.45,13.34 522.61,13.34 522.61,14.61 IC112.5
  Bottom 0.254: v508,246.38 515.62,246.38 517.52,244.47 IC117.3
N$117  (via drill 0.61)
  Top 0.254: v486.41,332.11 486.41,322.58 485.14,321.31 IC109.6 | IC140.13 596.26,536.58 597.53,536.58 IC140.12
  Bottom 0.254: v486.41,332.11 488.95,334.64 583.57,334.64 609.6,360.68 609.6,535.3 600.08,535.3 598.8,536.58 IC140.12
N$118  (via drill 0.61)
  Top 0.254: v563.88,118.75 572.77,127.64 v572.77,528.96 | IC140.9 605.15,536.58 603.88,536.58 IC140.10
  Bottom 0.254: v563.88,118.75 531.5,118.75 528.96,116.2 489.58,116.2 488.31,117.47 IC106.8 | v572.77,528.96 582.93,539.12 601.35,539.12 602.62,537.85 IC140.10
N$119  (via drill 0.61)
  Top 0.254: v509.9,212.09 508,210.19 508,21.59 513.08,16.51 IC112.1
  Bottom 0.254: v509.9,212.09 514.35,216.53 529.59,216.53 530.86,215.26 530.86,212.09 528.32,212.09 IC116.8
N$123
  Bottom 0.254: M916_3.D2 -32.38,474.98 -31.11,473.71 -22.23,473.71 -20.95,474.98 M916_3.J2
N$124  (via drill 0.61)
  Top 0.254: v29.84,419.74 29.84,266.06 28.57,264.8 v28.57,229.24 | v40.64,217.17 40.64,195.58 IC12.11
  Bottom 0.254: v29.84,419.74 4.45,419.74 0.64,423.55 IC4.11 | v40.64,217.17 v28.57,229.24
N$125  (via drill 0.61)
  Top 0.254: v10.16,543.56 17.14,536.58 17.14,388.62 18.41,387.35 v18.41,196.22
  Bottom 0.254: v10.16,543.56 8.89,544.83 0,544.83 -4.45,540.38 IC7.2 | v18.41,196.22 20.32,194.31 20.95,194.31 30.48,184.78 33.66,184.78 34.29,185.42 34.29,188.59 43.81,188.59 45.09,187.32 IC12.6
N$126
  Bottom 0.254: M916_3.E2 -29.21,478.79 -27.94,480.06 -19.05,480.06 -17.78,478.79 M916_3.K2
N$127
  Bottom 0.254: M916_13.D2 288.93,570.23 290.19,568.96 299.08,568.96 300.36,570.23 M916_13.J2
N$128
  Top 0.254: IC7.3 -2.54,538.48 -3.17,537.85 -3.17,452.75 -1.27,450.85 -1.27,429.26 2.54,425.45 IC4.10
N$129  (via drill 0.61)
  Top 0.254: v457.2,404.5 457.83,405.13 v457.83,526.41
  Bottom 0.254: v457.2,404.5 447.68,404.5 446.4,405.76 IC98.6 | v457.83,526.41 448.94,535.3 445.13,535.3 443.87,536.58 IC102.10
N$130
  Bottom 0.254: M916_13.E2 292.1,573.4 293.37,572.13 302.26,572.13 303.53,573.4 M916_13.K2
N$131
  Bottom 0.254: M916_4.D2 48.9,570.87 50.16,572.13 58.42,572.13 59.69,570.87 60.33,570.87 M916_4.J2
N$132  (via drill 0.61)
  Top 0.254: v-6.99,478.15 -6.35,477.52 -6.35,429.26 -2.54,425.45 IC4.12
  Bottom 0.254: v-6.99,478.15 14.61,499.75 34.92,499.75 35.56,500.38 35.56,503.56 40.01,503.56 41.27,502.29 IC6.4
N$133
  Bottom 0.254: M916_4.E2 52.07,574.04 53.34,575.31 62.23,575.31 63.5,574.04 M916_4.K2
N$134
  Bottom 0.254: M916_14.D2 328.3,56.52 329.56,57.78 335.28,57.78 336.55,56.52 339.73,56.52 M916_14.J2
N$135
  Bottom 0.254: M916_14.E2 331.47,59.05 332.11,58.42 335.92,58.42 336.55,57.78 341.63,57.78 342.9,59.05 M916_14.K2
N$136
  Bottom 0.254: M916_5.D2 88.27,56.52 89.53,57.78 97.79,57.78 99.06,56.52 99.69,56.52 M916_5.J2
N$137  (via drill 0.61)
  Top 0.254: v11.43,262.89 10.16,264.16 10.16,417.19 v10.79,417.83
  Bottom 0.254: v11.43,262.89 14.61,259.71 43.81,259.71 45.09,260.99 IC13.6 | v10.79,417.83 9.53,419.1 0,419.1 -4.45,423.55 IC4.13
N$138  (via drill 0.61)
  Top 0.254: v33.02,264.16 34.29,262.89 v34.29,184.15 | v24.77,180.97 25.4,180.34 25.4,81.28 29.21,77.47 29.21,24.13 36.2,17.14 41.91,17.14 41.91,13.97 42.55,13.34 45.09,13.34 45.09,14.61 IC9.6
  Bottom 0.254: v33.02,264.16 40.64,264.16 42.55,262.25 IC13.5 | v34.29,184.15 31.11,180.97 v24.77,180.97
N$139
  Bottom 0.254: IC13.3 38.73,260.99 40.01,260.99 IC13.4
N$140
  Bottom 0.254: M916_5.E2 91.44,59.69 92.71,60.96 101.6,60.96 102.87,59.69 M916_5.K2
N$142  (via drill 0.61)
  Top 0.254: v439.42,386.08 439.42,527.05 440.69,528.32 IC102.4
  Bottom 0.254: v439.42,386.08 448.31,377.19 IC97.8
N$146  (via drill 0.61)
  Top 0.254: v450.85,333.38 450.21,334.01 450.21,366.39 451.49,367.67 v451.49,451.49
  Bottom 0.254: v450.85,333.38 448.94,333.38 446.4,330.83 IC96.6 | v451.49,451.49 442.6,451.49 441.32,452.75 IC100.4
N$147  (via drill 0.61)
  Top 0.254: v449.58,456.56 449.58,416.56 448.31,415.29 IC98.8
  Bottom 0.254: v449.58,456.56 447.04,459.11 445.13,459.11 443.87,460.38 IC100.10
N$148  (via drill 0.61)
  Top 0.254: v455.93,366.39 459.11,369.57 v459.11,488.95
  Bottom 0.254: v455.93,366.39 447.68,366.39 446.4,367.67 IC97.6 | v459.11,488.95 458.47,489.58 442.6,489.58 441.32,490.86 IC101.4
N$150
  Top 0.254: M916_22.S2 1.27,389.89 1.27,395.61 M916_22.S1
N$151
  Bottom 0.254: M916_22.R2 -0.64,386.08 0.64,384.81 9.53,384.81 10.79,386.08 M916_22.V2
N$153  (via drill 0.61)
  Top 0.254: v45.72,180.97 45.72,121.92 48.26,119.38 IC11.8
  Bottom 0.254: v45.72,180.97 41.91,184.78 37.47,184.78 36.2,186.06 IC12.2
N$155  (via drill 0.61)
  Top 0.254: v518.16,69.22 519.43,70.48 519.43,77.47 518.16,78.74 IC113.12
  Bottom 0.254: v518.16,69.22 504.82,69.22 488.31,52.7 IC105.8
N$161  (via drill 0.61)
  Top 0.254: v43.18,106.05 43.18,73.66 44.45,72.39 44.45,55.88 45.72,54.61 IC10.6 | v33.02,115.57 34.29,116.84 34.29,159.38 33.02,160.66 33.02,179.07 39.37,185.42 v39.37,350.52
  Bottom 0.254: v43.18,106.05 41.27,107.95 33.02,107.95 31.75,109.22 31.75,115.57 v33.02,115.57 | v39.37,350.52 33.02,356.87 IC14.1
N$162  (via drill 0.61)
  Top 0.254: v35.56,271.78 35.56,356.87 IC14.2
  Bottom 0.254: IC13.10 42.55,269.88 41.27,271.14 40.01,271.14 38.73,269.88 IC13.12 37.47,269.88 v35.56,271.78
N$185  (via drill 0.61)
  Top 0.254: v516.89,548 516.89,516.89 517.52,516.25 521.97,516.25 521.97,519.43 522.61,520.07 540.38,520.07 540.38,412.75 537.85,410.21 537.85,326.39 538.48,325.75 538.48,179.07 540.38,177.16 v540.38,75.56
  Bottom 0.254: v516.89,548 475.62,548 446.4,577.22 IC103.6 | v540.38,75.56 535.3,70.48 522.61,70.48 521.97,71.12 521.97,74.3 517.52,74.3 516.25,73.03 IC113.2
N$193  (via drill 0.61)
  Top 0.254: v492.12,109.86 490.86,108.58 490.86,4.45 487.05,4.45 485.77,5.71 IC104.6
  Bottom 0.254: v492.12,109.86 494.67,112.39 513.72,112.39 514.99,111.12 IC114.2
NC  (via drill 0.61)
  Top 0.254: M916_14.L2 347.35,56.52 349.25,58.42 349.25,59.05 M916_14.M2 | v357.5,60.96 357.5,207.01 358.77,208.28 M916_16.R2 | SV4.L -17.78,140.34 -19.05,141.6 -19.05,153.03 -17.78,154.31 SV9.L -17.78,155.57 -31.11,168.91 v-31.11,233.04 | 13.97,155.57 14.61,156.21 17.78,156.21 17.78,155.57 SV9.TT | 13.97,155.57 13.34,154.94 SV9.NN | 13.97,155.57 13.97,141.6 12.7,140.34 SV4.NN | M916_5.M2 109.22,59.05 107.31,57.15 107.31,56.52 M916_5.L2 | 19.05,103.5 17.78,102.23 SV3.TT | 19.05,103.5 19.05,120.02 | 19.05,120.02 17.78,121.28 SV8.TT | v95.25,90.81 95.25,60.96 96.52,59.69 M916_5.H2 | v19.05,93.34 19.05,103.5 | 19.05,120.02 19.05,137.79 17.78,139.06 SV4.TT | M916_20.E1 -29.21,243.21 -27.3,241.3 -27.3,240.66 M916_20.F1 | M916_20.S2 1.27,236.85 1.27,232.41 0,231.14 -1.27,231.14 -1.27,233.68 M916_20.R2 | M916_13.L2 307.98,570.87 309.88,572.77 309.88,573.4 M916_13.M2 | M916_4.L2 67.94,570.87 69.85,572.77 69.85,573.4 M916_4.M2 | -12.06,476.88 -11.43,477.52 -11.43,478.15 M916_3.M2 | -12.7,476.25 -12.06,476.88 | -12.7,476.25 -13.34,475.62 M916_3.L2 | -12.7,476.25 -9.53,473.07 -9.53,335.92 -11.43,334.01 -11.43,321.31 -12.06,320.68 -12.06,314.32 -11.43,313.69 M916_21.M2 -11.43,313.06 v-11.43,300.99 | -12.06,476.88 -12.06,587.38 40.01,587.38 52.7,574.67 52.7,574.04 57.15,574.04 M916_4.H2
  Bottom 0.254: 347.98,60.96 339.09,60.96 337.82,59.69 M916_14.H2 336.55,59.69 335.28,60.96 207.01,60.96 205.1,59.05 131.44,59.05 129.54,60.96 111.76,60.96 110.49,59.69 M916_5.M2 | 347.98,60.96 349.25,59.69 M916_14.M2 | 347.98,60.96 v357.5,60.96 | SV4.L -17.14,139.7 -15.88,140.97 -14.61,140.97 -13.34,139.7 SV4.R -12.06,139.7 -10.79,140.97 14.61,140.97 | SV9.L -17.14,154.94 -15.88,156.21 -14.61,156.21 -13.34,154.94 SV9.R | 14.61,140.97 13.34,139.7 SV4.NN | 14.61,140.97 15.88,140.97 17.14,139.7 SV4.TT | M916_5.H2 97.79,59.05 99.06,57.78 104.78,57.78 106.05,56.52 M916_5.L2 | SV3.NN 13.34,101.6 14.61,102.87 15.88,102.87 17.14,101.6 SV3.TT | SV8.NN 13.34,121.92 14.61,123.19 15.88,123.19 17.14,121.92 SV8.TT | v95.25,90.81 92.71,93.34 v19.05,93.34 | 80.01,286.38 81.28,285.12 M916_8.B2 | 80.01,286.38 78.74,287.65 M916_8.A2 77.47,287.65 74.3,284.48 -11.43,284.48 | 80.01,286.38 98.42,286.38 99.69,285.12 M916_8.J2 | M916_20.P2 -3.81,236.85 1.27,236.85 M916_20.S2 2.54,236.85 7.62,236.85 M916_20.U2 | M916_20.R2 -1.91,233.68 -6.99,233.68 M916_20.N2 -8.26,234.31 -8.89,234.95 -12.7,234.95 -17.78,240.03 -19.68,240.03 M916_20.J1 -20.95,240.03 -26.04,240.03 M916_20.F1 -27.3,240.03 -28.57,238.76 -31.11,238.76 | -31.11,238.76 -37.47,238.76 -38.73,240.03 M916_20.B1 | -11.43,284.48 -29.21,266.7 -29.21,243.84 M916_20.E1 | M916_13.M2 309.88,574.04 308.61,575.31 299.72,575.31 298.45,574.04 M916_13.H2 297.18,574.04 295.91,575.31 288.93,575.31 285.75,572.13 65.41,572.13 | 65.41,572.13 59.69,572.13 58.42,573.4 M916_4.H2 | 65.41,572.13 66.67,570.87 M916_4.L2 | M916_3.H2 -22.86,478.15 -21.59,476.88 -17.14,476.88 -15.88,475.62 -14.61,475.62 M916_3.L2
  Bottom 0.254: M916_21.M2 -10.16,313.06 -5.08,313.06 M916_21.P2 -3.81,313.69 -2.54,314.96 2.54,314.96 4.45,313.06 4.45,310.51 M916_21.T2 4.45,309.88 -0.64,309.88 M916_21.R2 | -11.43,284.48 v-11.43,300.99 | v-31.11,233.04 -31.11,238.76
PAR  (via drill 0.61)
  Top 0.254: v5.08,534.67 5.08,538.48 IC7.6 | v91.44,512.45 95.89,508 v95.89,367.67
  Bottom 0.254: v5.08,534.67 27.3,512.45 v91.44,512.45 | v95.89,367.67 97.79,365.76 123.83,365.76 125.09,367.03 M916_9.T1
PAR\  (via drill 0.61)
  Top 0.254: v8.89,537.85 16.51,530.23 16.51,387.99 17.14,387.35 17.14,349.88 15.88,348.62 v15.88,272.42 15.88,238.76 v17.14,237.49 | v208.28,227.97 208.28,214.63 IC38.8
  Bottom 0.254: v8.89,537.85 4.45,537.85 3.17,539.12 IC7.5 | v15.88,272.42 17.14,271.14 33.66,271.14 34.92,269.88 IC13.13 | v208.28,227.97 207.01,229.24 138.43,229.24 132.08,235.59 93.98,235.59 93.34,234.95 19.68,234.95 v17.14,237.49
PC+ES
  Top 0.254: IC13.8 48.26,270.51 46.99,271.78 46.99,363.22 45.72,364.49 IC14.9
PC+ES\  (via drill 0.61)
  Top 0.254: v142.88,356.87 147.96,361.95 147.96,431.8 148.59,432.44 v148.59,544.83
  Bottom 0.254: v142.88,356.87 141.6,355.6 135.25,355.6 133.35,357.5 82.55,357.5 79.38,360.68 53.34,360.68 48.9,365.12 IC14.8 | v148.59,544.83 149.22,545.47 281.31,545.47 283.21,547.37 IC69.5
PWR_CLR\  (via drill 0.61)
  Top 0.254: IC136.1 593.09,378.46 595.63,381 595.63,383.54 IC136.13 | v542.92,469.9 544.2,468.63 v544.2,388.62 v544.2,184.15 | IC13.9 45.72,267.97 44.45,266.7 44.45,259.08 43.18,257.81 43.18,195.58 IC12.10 | v111.12,194.94 111.12,217.17 110.49,217.81 M916_7.M1 | v284.48,196.22 284.48,189.23 283.21,187.96 IC61.5 | v444.5,194.31 v444.5,157.48 444.5,132.08 443.23,130.81 IC93.5 | v515.62,170.81 515.62,157.48 IC115.13
  Bottom 0.254: v542.92,469.9 407.67,469.9 405.76,471.81 IC90.6 | v544.2,388.62 556.26,376.56 592.46,376.56 IC136.1 | 41.27,196.22 28.57,196.22 28.57,192.41 33.02,187.96 IC12.1 | 41.27,196.22 42.55,194.94 IC12.10 | 41.27,196.22 48.9,196.22 49.53,195.58 110.49,195.58 v111.12,194.94 111.76,195.58 234.95,195.58 235.59,196.22 253.37,196.22 254,195.58 271.78,195.58 272.42,196.22 v284.48,196.22 309.25,196.22 311.79,193.68 330.2,193.68 331.47,194.94 444.5,194.94 | IC115.4 521.34,147.96 522.61,146.69 526.41,146.69 527.05,147.32 527.05,153.03 522.61,153.03 521.34,154.31 520.07,154.31 519.43,154.94 519.43,158.12 517.52,158.12 516.25,156.84 IC115.13 514.99,156.84 513.72,158.12 445.13,158.12 v444.5,157.48 | 444.5,194.94 470.54,194.94 471.81,196.22 473.07,196.22 474.35,194.94 IC107.13 | 444.5,194.94 v444.5,194.31 | v544.2,184.15 530.86,170.81 v515.62,170.81
RD+WD  (via drill 0.61)
  Top 0.254: v262.25,108.58 v262.25,36.83 262.25,5.08 49.53,5.08 40.64,13.97 IC9.4 | v322.58,38.1 325.12,40.64 IC71.9 | v474.98,323.85 474.98,321.31 IC109.2 | v453.39,323.85 450.85,321.31 v450.85,41.27
  Bottom 0.254: v262.25,108.58 269.24,115.57 285.75,115.57 287.65,117.47 IC60.8 | v322.58,38.1 321.94,37.47 262.89,37.47 v262.25,36.83 | v453.39,323.85 v474.98,323.85 | v450.85,41.27 449.58,40.01 327.02,40.01 325.75,41.27 IC71.9
RD_EN  (via drill 0.61)
  Top 0.254: v483.24,184.15 481.33,182.25 481.33,113.03 482.6,111.76 IC106.5
  Bottom 0.254: v483.24,184.15 482.6,184.78 479.43,184.78 478.15,186.06 IC107.3
RD_EN_LPB_00-02  (via drill 0.61)
  Top 0.254: v523.24,123.19 523.24,120.65 524.51,119.38 524.51,21.59 525.14,20.95 525.14,17.14 525.78,16.51 IC112.6 | v601.98,140.34 603.25,141.6 603.25,157.48 IC129.5 603.25,160.02 603.25,161.93 601.98,163.19 601.98,194.31 603.25,195.58 IC130.5 | v603.25,325.12 601.98,323.85 601.98,245.11 603.25,243.84 IC131.10
  Bottom 0.254: v523.24,123.19 540.38,140.34 v601.98,140.34 | IC131.10 603.25,241.3 603.25,236.85 603.88,236.85 604.52,236.22 604.52,206.38 602.62,206.38 601.98,205.74 601.98,198.12 603.25,198.12 IC130.5 | v603.25,325.12 610.24,325.12 610.24,537.85 608.33,539.75 598.8,539.75 558.16,580.39 435.61,580.39 433.7,578.49 IC103.1
RD_EN_LPB_03-05  (via drill 0.61)
  Top 0.254: v474.98,41.27 474.98,43.18 IC105.2 | v513.08,33.02 514.35,31.75 514.35,17.78 515.62,16.51 IC112.2 | IC131.5 603.25,233.68 603.25,205.74 IC130.10 | v586.74,162.56 v586.74,68.58
  Bottom 0.254: v474.98,41.27 483.24,33.02 v513.08,33.02 525.14,45.09 563.25,45.09 v586.74,68.58 | 603.25,168.91 603.25,191.77 607.06,195.58 607.06,202.56 605.15,202.56 603.88,203.84 IC130.10 | 603.25,168.91 603.25,167.64 IC129.10 | v586.74,162.56 593.09,168.91 603.25,168.91
RDD_00  (via drill 0.61)
  Top 0.254: v279.4,199.39 279.4,220.34 276.86,222.88 276.86,287.02 278.13,288.29 IC63.12 | v131.44,201.29 127,196.85 127,60.96 128.27,59.69 M916_5.U2 | v340.36,170.81 337.19,173.99 v337.19,197.49
  Bottom 0.254: 600.71,161.29 600.71,164.47 603.88,164.47 605.15,165.74 IC129.9 | 600.71,161.29 600.71,160.02 IC129.4 | v131.44,201.29 133.99,201.29 135.89,203.2 158.75,203.2 162.56,199.39 v279.4,199.39 335.28,199.39 v337.19,197.49 | 600.71,161.29 542.29,161.29 541.65,160.66 539.75,160.66 533.4,167 489.58,167 488.95,166.37 483.24,166.37 482.6,165.74 432.44,165.74 427.36,170.81 v340.36,170.81
RDD_01  (via drill 0.61)
  Top 0.254: IC130.9 605.79,205.74 607.06,207.01 607.06,240.03 605.79,241.3 IC131.9 | v278.13,296.55 278.13,316.23 275.59,318.77 IC64.2 | v348.62,296.55 351.15,296.55 v351.15,200.03 351.15,198.75 348.62,196.22 v348.62,64.77
  Bottom 0.254: v348.62,296.55 v278.13,296.55 | v348.62,64.77 349.25,64.14 361.95,64.14 366.39,59.69 368.3,59.69 M916_14.U2 | v351.15,200.03 527.68,200.03 560.07,232.41 601.98,232.41 601.98,243.84 602.62,244.47 603.88,244.47 605.15,243.21 IC131.9
RDD_02  (via drill 0.61)
  Top 0.254: 601.98,232.41 601.98,199.39 600.71,198.12 IC130.4 | 601.98,232.41 600.71,233.68 IC131.4 | v278.13,258.44 278.13,252.73 IC62.12 | v600.71,245.11 601.98,243.84 601.98,232.41 | v109.86,391.16 109.86,487.68 116.2,494.03 116.2,518.79 111.76,523.24 111.76,573.4 90.17,573.4 M916_4.U2 | v256.54,389.25 256.54,340.36 267.97,328.93 v267.97,258.44
  Bottom 0.254: v600.71,245.11 588.01,257.81 347.35,257.81 346.07,256.54 290.19,256.54 288.93,257.81 278.76,257.81 v278.13,258.44 277.5,259.08 268.61,259.08 v267.97,258.44 | v109.86,391.16 161.29,391.16 163.19,389.25 v256.54,389.25
READ_ALL\  (via drill 0.61)
  Top 0.254: v551.18,131.44 555.62,135.89 555.62,418.46 554.99,419.1 | 554.99,419.1 553.72,420.37 IC124.4 | 554.99,419.1 554.99,516.89 557.53,519.43 IC125.3
  Bottom 0.254: v551.18,131.44 541.65,121.92 478.79,121.92 475.62,118.75 IC106.13
READ_DATA  (via drill 0.61)
  Top 0.254: v561.98,114.3 573.4,125.73 573.4,418.46 575.31,420.37 575.31,527.68 572.13,530.86 556.26,530.86 556.26,523.24 554.99,521.97 IC125.2 | v41.27,122.56 41.27,184.78 40.64,185.42 IC12.4 | v389.25,118.11 v380.37,127
  Bottom 0.254: 481.96,112.39 483.87,114.3 v561.98,114.3 | 481.96,112.39 480.69,111.12 IC106.4 | v41.27,122.56 225.43,122.56 229.87,127 v380.37,127 | v389.25,118.11 391.8,115.57 440.69,115.57 443.87,112.39 481.96,112.39
READ_DATA\  (via drill 0.61)
  Top 0.254: IC124.3 551.18,422.91 549.91,424.18 549.91,516.89 552.45,519.43 IC125.1 | v283.21,184.15 285.75,181.61 285.75,119.38 IC60.9 | v271.14,184.15 271.14,253.37 271.78,254 271.78,279.4 271.14,280.04 271.14,291.46 272.42,292.74 272.42,316.87 271.14,318.13 271.14,368.3 272.42,369.57 272.42,392.43 271.14,393.7 271.14,492.76 | 271.14,492.76 271.14,545.47 273.05,547.37 IC69.1 | 271.14,492.76 v271.78,492.76
  Bottom 0.254: v271.14,184.15 v283.21,184.15 | v271.78,492.76 302.89,492.76 315.6,505.46 538.48,505.46 552.45,519.43 IC125.1
RSTA\  (via drill 0.61)
  Top 0.254: IC32.3 157.48,547.37 157.48,481.33 IC31.12 157.48,478.79 157.48,473.71 IC31.3 157.48,471.17 157.48,405.13 IC30.12 157.48,402.59 157.48,397.51 IC30.3 | IC31.6 165.1,473.71 165.1,478.79 IC31.9 165.1,481.33 v165.1,513.08 165.1,547.37 IC32.6 | v244.47,513.72 244.47,516.25 245.11,516.89 IC55.9 | IC30.9 165.1,402.59 165.1,397.51 IC30.6 165.1,394.97 165.1,388.62 v170.18,383.54 | v408.94,372.75 v408.94,248.92
  Bottom 0.254: v244.47,513.72 243.84,513.08 v165.1,513.08 | IC31.3 158.12,473.07 159.38,474.35 163.19,474.35 164.47,473.07 IC31.6 | v408.94,248.92 405.13,245.11 IC87.6 | v408.94,372.75 407.67,374.01 331.47,374.01 326.39,379.1 212.72,379.1 208.28,383.54 v170.18,383.54 | IC30.3 158.12,396.88 159.38,398.14 163.19,398.14 164.47,396.88 IC30.6
RSTB\  (via drill 0.61)
  Top 0.254: IC38.3 198.12,207.01 198.12,212.09 IC38.12 198.12,214.63 198.12,280.67 IC39.3 198.12,283.21 198.12,288.29 IC39.12 | IC38.6 205.74,207.01 205.74,212.09 IC38.9 | IC39.6 205.74,283.21 205.74,288.29 IC39.9 205.74,290.83 206.38,291.46 206.38,396.88 v204.47,398.78 | IC88.11 400.05,386.08 400.69,386.71 400.69,394.33 401.32,394.97 401.32,468.63 403.86,471.17 403.86,492.76 403.23,493.39 397.51,493.39 397.51,492.76 IC91.3 | v316.87,551.82 349.25,519.43 v349.25,489.58 | v166.37,401.32 166.37,552.45 165.1,553.72 165.1,554.99 IC32.9
  Bottom 0.254: IC38.3 198.75,205.1 200.03,203.84 203.84,203.84 205.1,205.1 IC38.6 | IC39.12 198.75,290.19 200.03,291.46 203.84,291.46 205.1,290.19 IC39.9 | IC32.12 158.12,555.62 159.38,554.36 163.19,554.36 164.47,555.62 IC32.9 165.74,556.89 167,558.16 310.51,558.16 v316.87,551.82 | v349.25,489.58 349.88,488.95 394.97,488.95 396.88,490.86 IC91.3 | v204.47,398.78 201.93,401.32 v166.37,401.32
SE\  (via drill 0.61)
  Top 0.254: v552.45,426.72 552.45,438.15 553.72,439.42 553.72,525.78 554.99,527.05 IC125.13 554.36,528.96 v500.38,582.93
  Bottom 0.254: v552.45,426.72 555.62,423.55 561.98,423.55 563.25,422.27 IC124.8 | v500.38,582.93 433.07,582.93 431.8,584.2 177.8,584.2 177.16,583.57 4.45,583.57 3.17,584.84 IC8.10
SEARCH  (via drill 0.61)
  Top 0.254: v556.89,79.38 556.89,24.77 557.53,24.13 IC123.12
  Bottom 0.254: v556.89,79.38 530.23,106.05 476.88,106.05 473.07,109.86 IC106.1
SEARCH\  (via drill 0.61)
  Top 0.254: v236.22,36.83 236.22,88.9 234.95,90.17 IC47.2 | v552.45,28.57 554.99,26.04 554.99,24.13 IC123.13 | v283.85,540.38 276.23,548 IC69.2 | v474.35,539.75 509.27,504.82 v509.27,424.81 | v535.94,29.84 536.58,30.48 536.58,323.85 534.67,325.75 534.67,420.37 534.03,421 534.03,424.18 v534.67,424.81
  Bottom 0.254: v236.22,36.83 243.84,29.21 437.51,29.21 438.15,28.57 535.94,28.57 | 535.94,28.57 v552.45,28.57 | v283.85,540.38 284.48,539.75 v474.35,539.75 | v509.27,424.81 v534.67,424.81 545.47,424.81 548,422.27 IC124.2 | 535.94,28.57 v535.94,29.84
SEL  (via drill 0.61)
  Top 0.254: v122.56,449.58 122.56,370.84 M916_9.S1
  Bottom 0.254: v122.56,449.58 55.88,449.58 53.98,447.68 6.99,447.68 5.71,448.94 IC5.9
SEL\  (via drill 0.61)
  Top 0.254: v57.15,57.15 59.69,59.69 v59.69,156.84 58.42,158.12 58.42,163.83 v55.24,167 | v201.93,164.47 203.2,165.74 203.2,204.47 IC38.5 | v20.32,448.94 23.5,445.77 v23.5,171.45
  Bottom 0.254: v57.15,57.15 46.99,57.15 43.81,53.98 IC10.5 | v59.69,156.84 67.31,164.47 v201.93,164.47 | v20.32,448.94 8.26,448.94 IC5.8 | v23.5,171.45 27.94,167 v55.24,167
SH_DTB  (via drill 0.61)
